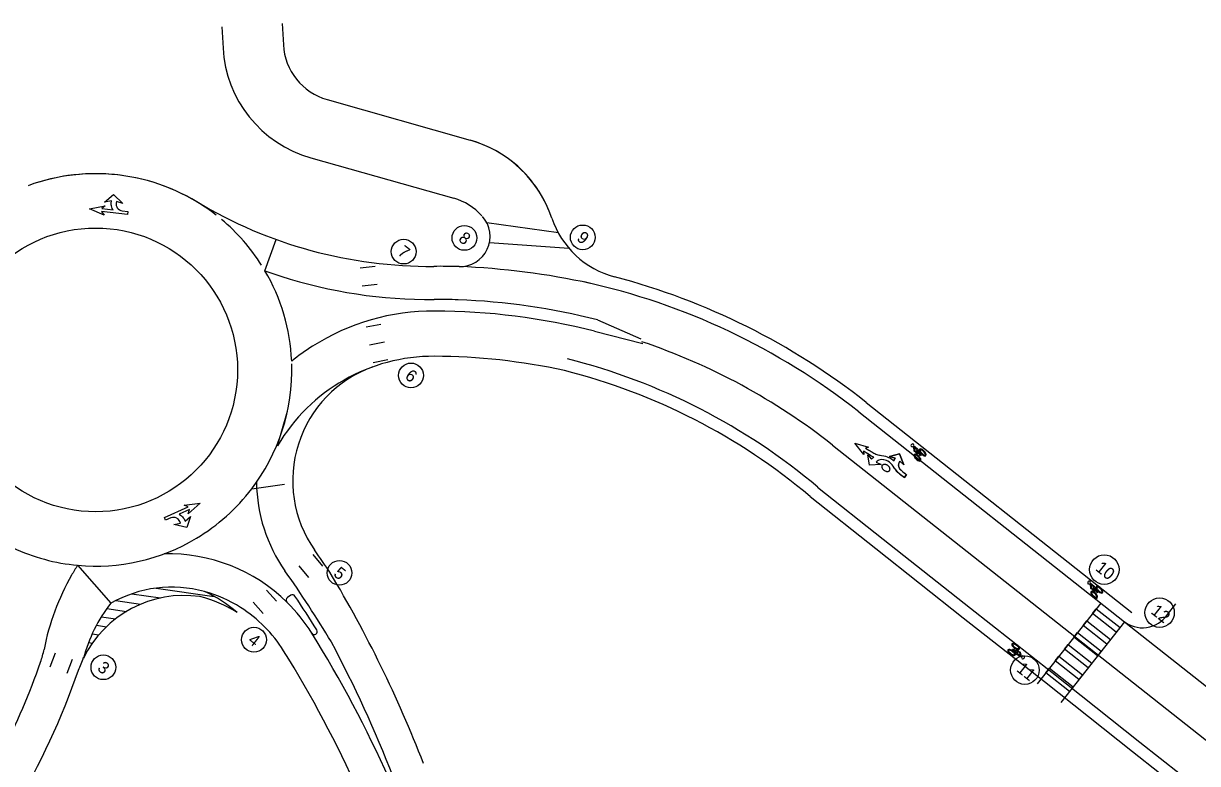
# Model space of a CAD drawing. Extents: x 553958 to 562499, y 493978 to 516388.
# Drawn here: x 561765 to 562153.9, y 497670.2 to 497915.3 of the extents above; entities that cross this region are included whole.
import ezdxf

# ---------------------------------------------------------------- set-up
doc = ezdxf.new("R2010")
doc.units = 0
for name, color, linetype in [('Exist Horizontal Alignment', 7, 'Continuous'), ('Old_Level_1', 7, 'Continuous'), ('Prop Conc Shoulder Berm Gutter', 7, 'Continuous'), ('Prop Dimension', 7, 'Continuous'), ('Prop Drainage Structure Gutter Shoulder Berm Label', 7, 'Continuous'), ('Prop DSN Text', 7, 'Continuous'), ('Prop EOT', 7, 'Continuous'), ('Prop Horizontal Alignment Tick Small', 7, 'Continuous'), ('Prop SS Cut Line', 7, 'Continuous'), ('Prop SS Fill Line', 7, 'Continuous'), ('Prop SS Transition Line', 7, 'Continuous'), ('Scratch_Level_4', 7, 'Continuous'), ('Sheet Plot Border Inside CELL', 7, 'Continuous'), ('Sheet Plot Border Outside CELL', 7, 'Continuous')]:
    doc.layers.add(name, color=color, linetype=linetype)

msp = doc.modelspace()

# ---------------------------------------------------------------- linework, layer by layer
at = {"layer": 'Exist Horizontal Alignment'}
msp.add_circle((561788.88, 497800.56), 47, dxfattribs=at)
at = {"layer": 'Old_Level_1'}
for centre, radius, start, end in [((561902.83, 497610.87), 213, 88.3516, 90.4946), ((561900.37, 497600.07), 220, 75.852, 89.7953), ((561900.37, 497600.07), 220, 75.852, 89.7953), ((561742.33, 497713.69), 30, 340.6791, 349.0323)]:
    msp.add_arc(centre, radius, start, end, dxfattribs=at)
at = {"layer": 'Prop Conc Shoulder Berm Gutter'}
for p, q in [((561840.59, 497761.18), (561851.48, 497762.72)), ((561782.89, 497735.84), (561793.95, 497723.27))]:
    msp.add_line(p, q, dxfattribs=at)
msp.add_lwpolyline([(561844.97, 497833.41), (561848.7, 497843.76), (561848.7, 497843.76)], dxfattribs=at)
at = {"layer": 'Prop Dimension'}
msp.add_arc((561902.83, 497610.87), 228, 51.6978, 75.2698, dxfattribs=at)
at = {"layer": 'Prop Drainage Structure Gutter Shoulder Berm Label'}
for points in [[(561799.47, 497852.06), (561790.85, 497852.99), (561791.73, 497851.81), (561786.84, 497853.93), (561792.07, 497854.95), (561790.96, 497853.99), (561794.71, 497853.58), (561794.39, 497854.07), (561794.22, 497854.45), (561794.11, 497854.91), (561794.07, 497855.28), (561794.06, 497855.75), (561794.17, 497856.57), (561791.86, 497856.15), (561794.74, 497858.69), (561797.93, 497855.66), (561795.74, 497856.4), (561795.69, 497855.75), (561795.66, 497855.37), (561795.72, 497854.98), (561795.86, 497854.62), (561796.01, 497854.27), (561796.32, 497853.9), (561796.73, 497853.6), (561797.17, 497853.39), (561797.69, 497853.25), (561799.57, 497853.05)], [(561799.47, 497852.06), (561790.85, 497852.99), (561791.73, 497851.81), (561786.84, 497853.93), (561792.07, 497854.95), (561790.96, 497853.99), (561794.71, 497853.58), (561794.39, 497854.07), (561794.22, 497854.45), (561794.11, 497854.91), (561794.07, 497855.28), (561794.06, 497855.75), (561794.17, 497856.57), (561791.86, 497856.15), (561794.74, 497858.69), (561797.93, 497855.66), (561795.74, 497856.4), (561795.69, 497855.75), (561795.66, 497855.37), (561795.72, 497854.98), (561795.86, 497854.62), (561796.01, 497854.27), (561796.32, 497853.9), (561796.73, 497853.6), (561797.17, 497853.39), (561797.69, 497853.25), (561799.57, 497853.05)], [(561811.63, 497751.64), (561819.54, 497755.19), (561818.18, 497755.77), (561823.47, 497756.41), (561819.48, 497752.88), (561819.95, 497754.28), (561816.51, 497752.74), (561817.03, 497752.47), (561817.36, 497752.23), (561817.69, 497751.89), (561817.92, 497751.59), (561818.16, 497751.19), (561818.48, 497750.43), (561820.26, 497751.96), (561819.07, 497748.31), (561814.78, 497749.31), (561817.04, 497749.78), (561816.76, 497750.36), (561816.59, 497750.71), (561816.34, 497751.02), (561816.04, 497751.25), (561815.73, 497751.48), (561815.27, 497751.65), (561814.77, 497751.7), (561814.28, 497751.66), (561813.77, 497751.51), (561812.04, 497750.73)], [(561811.63, 497751.64), (561819.54, 497755.19), (561818.18, 497755.77), (561823.47, 497756.41), (561819.48, 497752.88), (561819.95, 497754.28), (561816.51, 497752.74), (561817.03, 497752.47), (561817.36, 497752.23), (561817.69, 497751.89), (561817.92, 497751.59), (561818.16, 497751.19), (561818.48, 497750.43), (561820.26, 497751.96), (561819.07, 497748.31), (561814.78, 497749.31), (561817.04, 497749.78), (561816.76, 497750.36), (561816.59, 497750.71), (561816.34, 497751.02), (561816.04, 497751.25), (561815.73, 497751.48), (561815.27, 497751.65), (561814.77, 497751.7), (561814.28, 497751.66), (561813.77, 497751.51), (561812.04, 497750.73)]]:
    msp.add_lwpolyline(points, close=True, dxfattribs=at)
at = {"layer": 'Prop DSN Text'}
for centre, radius in [((561911.07, 497844.28), 4.11), ((561950.26, 497844.46), 4.1), ((561890.93, 497839.75), 4.1), ((561893.35, 497798.72), 4.1), ((562123.04, 497734.41), 4.89), ((561869.66, 497733.33), 4.09), ((562141.37, 497720.15), 4.87), ((561841.33, 497711.17), 4.12), ((561791.43, 497702.04), 4.09), ((562096.72, 497701.12), 4.73)]:
    msp.add_circle(centre, radius, dxfattribs=at)
at = {"layer": 'Prop EOT'}
msp.add_line((561849.14, 497775.43), (561852.42, 497786.87), dxfattribs=at)
msp.add_lwpolyline([(562043.41, 497772.58), (562040.35, 497776.27), (562044.97, 497774.99), (562043.97, 497774.69), (562045.06, 497773.99), (562045.43, 497773.75), (562045.79, 497773.52), (562046.01, 497773.39), (562046.37, 497773.18), (562046.68, 497772.99), (562046.99, 497772.83), (562047.4, 497772.65), (562047.72, 497772.54), (562047.97, 497772.47), (562048.17, 497772.42), (562048.53, 497772.34), (562048.82, 497772.29), (562049.25, 497772.23), (562049.98, 497772.11), (562050.51, 497771.98), (562051.11, 497771.78), (562051.59, 497771.59), (562052.18, 497771.28), (562052.67, 497770.97), (562053, 497770.72), (562053.37, 497770.39), (562053.47, 497770.67), (562053.62, 497771), (562053.76, 497771.28), (562051.91, 497771.84), (562055.23, 497772.76), (562056.63, 497769.12), (562055.26, 497770.33), (562055.08, 497769.96), (562054.99, 497769.77), (562054.92, 497769.59), (562054.87, 497769.41), (562054.83, 497769.25), (562054.8, 497768.98), (562054.81, 497768.83), (562054.87, 497768.56), (562054.92, 497768.42), (562054.99, 497768.25), (562055.1, 497768.05), (562055.24, 497767.85), (562055.36, 497767.72), (562055.61, 497767.44), (562055.83, 497767.21), (562056.08, 497766.97), (562056.36, 497766.73), (562056.6, 497766.54), (562056.93, 497766.3), (562057.22, 497766.11), (562057.49, 497765.95), (562056.82, 497764.92), (562056.51, 497765.13), (562055.89, 497765.57), (562055.28, 497766.04), (562054.69, 497766.55), (562054.31, 497766.95), (562053.93, 497767.42), (562053.68, 497767.79), (562053.47, 497768.15), (562053.13, 497768.67), (562052.75, 497769.16), (562052.37, 497769.58), (562051.93, 497769.95), (562051.38, 497770.3), (562050.9, 497770.53), (562050.45, 497770.68), (562050.01, 497770.8), (562049.85, 497770.8), (562049.21, 497770.83), (562048.81, 497770.8), (562048.35, 497770.67), (562048.07, 497770.53), (562047.84, 497770.36), (562047.45, 497769.96), (562049.12, 497769.2), (562045.23, 497768.99), (562044.71, 497772.39), (562045.97, 497770.94), (562046.16, 497771.2), (562046.33, 497771.38), (562046.54, 497771.56), (562046.64, 497771.64), (562046.17, 497771.88), (562045.66, 497772.15), (562045.23, 497772.42), (562044.69, 497772.77), (562043.26, 497773.69)], close=True, dxfattribs=at)
for points in [[(562055.26, 497770.33), (562056.63, 497769.12), (562055.23, 497772.76), (562051.91, 497771.84), (562053.76, 497771.28)], [(562056.82, 497764.92), (562057.49, 497765.95)]]:
    msp.add_lwpolyline(points, dxfattribs=at)
for centre, radius, start, end in [((561899.51, 497586.03), 248.94, 77.6632, 87.7507), ((562058.77, 497768.52), 5.72, 151.1501, 160.8548), ((562059.61, 497767.91), 4.97, 150.9846, 159.0255), ((562050.12, 497768.47), 0.777, 171.4542, 191.6551), ((562050.09, 497768.48), 0.742, 148.3406, 171.4542), ((562050.73, 497768.6), 1.4, 191.6551, 214.3846), ((562049.98, 497768.55), 0.613, 147.1072, 148.3406), ((562049.98, 497768.55), 0.613, 145.8738, 147.1072), ((562050.08, 497768.47), 0.742, 122.7602, 145.8738), ((562051.23, 497768.94), 2.01, 214.3846, 222.3695), ((562050.1, 497768.44), 0.777, 102.5592, 122.7602), ((562051.3, 497769.01), 2.1, 222.3695, 235.0686), ((562050.24, 497767.84), 1.4, 79.8298, 102.5592), ((562051.23, 497768.91), 1.98, 235.0686, 237.1072), ((562051.23, 497768.91), 1.98, 237.1072, 239.1457), ((562051.29, 497769.01), 2.1, 239.1457, 251.8449), ((562050.13, 497767.23), 2.01, 71.8449, 79.8298), ((562051.27, 497768.92), 2.01, 251.8449, 259.8298), ((562050.1, 497767.15), 2.1, 59.1457, 71.8449), ((562051.16, 497768.32), 1.4, 259.8298, 282.5592), ((562050.16, 497767.25), 1.98, 57.1072, 59.1457), ((562050.16, 497767.25), 1.98, 55.0686, 57.1072), ((562050.09, 497767.15), 2.1, 42.3695, 55.0686), ((562051.29, 497767.71), 0.777, 282.5592, 302.7602), ((562050.16, 497767.21), 2.01, 34.3846, 42.3695), ((562051.31, 497767.68), 0.742, 302.7602, 325.8738), ((562050.67, 497767.56), 1.4, 11.6551, 34.3846), ((562051.42, 497767.61), 0.613, 327.1072, 328.3406), ((562051.42, 497767.61), 0.613, 325.8738, 327.1072), ((562051.31, 497767.68), 0.742, 328.3406, 351.4542), ((562051.27, 497767.69), 0.777, 351.4542, 11.6551), ((562042.44, 497761.49), 12.88, 28.8167, 31.1161), ((562059.72, 497771.72), 7.21, 213.8512, 231.8501), ((562056.74, 497768.92), 1.93, 156.5912, 179.6833), ((562056.67, 497769.08), 1.88, 184.3573, 200.5072), ((562056.85, 497769.16), 2.07, 201.0235, 219.2305), ((562061.6, 497773.07), 8.23, 219.4223, 240.017), ((562069.38, 497783.85), 22.71, 231.5884, 236.4475)]:
    msp.add_arc(centre, radius, start, end, dxfattribs=at)
at = {"layer": 'Prop Horizontal Alignment Tick Small'}
for p, q in [((562059.15, 497775.07), (562059.26, 497775.18)), ((562059.15, 497775.07), (562059.26, 497775.18)), ((562059.85, 497775.75), (562059.96, 497775.86)), ((562059.85, 497775.75), (562059.96, 497775.86)), ((562059.96, 497774.99), (562060.12, 497775.28)), ((562060.02, 497773.65), (562059.96, 497774.99)), ((562060.12, 497775.28), (562061.36, 497774.15)), ((562060.99, 497774.07), (562060.18, 497774.8)), ((562060.18, 497774.8), (562060.24, 497773.43)), ((562060.59, 497773.14), (562060.99, 497774.07)), ((562061.36, 497774.15), (562062.24, 497772.23)), ((562060.24, 497773.43), (562060.02, 497773.65)), ((562061.29, 497772.67), (562060.59, 497773.14)), ((562060.85, 497771.23), (562060.68, 497771.06)), ((562060.85, 497771.23), (562060.68, 497771.06)), ((562061.19, 497773.94), (562060.89, 497773.22)), ((562060.89, 497773.22), (562061.43, 497772.86)), ((562062.03, 497772.13), (562061.19, 497773.94)), ((562061.43, 497772.86), (562061.29, 497772.67)), ((562061.61, 497771.97), (562061.44, 497771.8)), ((562061.61, 497771.97), (562061.44, 497771.8)), ((562062.24, 497772.23), (562062.04, 497772.11)), ((562062.6, 497772.93), (562062.43, 497772.76)), ((562062.6, 497772.93), (562062.43, 497772.76)), ((562063.36, 497773.67), (562063.19, 497773.5)), ((562063.36, 497773.67), (562063.19, 497773.5)), ((562117.7, 497729.63), (562117.81, 497729.74)), ((562117.7, 497729.63), (562117.81, 497729.74)), ((562118.4, 497730.31), (562118.51, 497730.41)), ((562118.4, 497730.31), (562118.51, 497730.41)), ((562118.51, 497729.55), (562118.67, 497729.83)), ((562118.57, 497728.2), (562118.51, 497729.55)), ((562118.78, 497727.98), (562118.57, 497728.2)), ((562118.67, 497729.83), (562119.9, 497728.71)), ((562119.54, 497728.62), (562118.73, 497729.36)), ((562118.73, 497729.36), (562118.78, 497727.98)), ((562119.14, 497727.69), (562119.54, 497728.62)), ((562119.84, 497727.22), (562119.14, 497727.69)), ((562119.74, 497728.5), (562119.43, 497727.78)), ((562119.43, 497727.78), (562119.97, 497727.42)), ((562120.57, 497726.69), (562119.74, 497728.5)), ((562119.97, 497727.42), (562119.84, 497727.22)), ((562119.9, 497728.71), (562120.79, 497726.79)), ((562121.15, 497727.49), (562120.98, 497727.32)), ((562121.15, 497727.49), (562120.98, 497727.32)), ((562121.91, 497728.23), (562121.74, 497728.06)), ((562121.91, 497728.23), (562121.74, 497728.06)), ((562119.4, 497725.78), (562119.22, 497725.61)), ((562119.4, 497725.78), (562119.22, 497725.61)), ((562120.16, 497726.52), (562119.98, 497726.35)), ((562120.16, 497726.52), (562119.98, 497726.35)), ((562120.79, 497726.79), (562120.58, 497726.66)), ((562092.75, 497708.05), (562092.93, 497708.21)), ((562093.99, 497706.34), (562092.75, 497708.05)), ((562092.94, 497708.19), (562094.11, 497706.58)), ((562093.32, 497708.43), (562093.46, 497708.63)), ((562093.32, 497708.43), (562093.46, 497708.63)), ((562093.92, 497709.3), (562094.06, 497709.5)), ((562093.92, 497709.3), (562094.06, 497709.5)), ((562091.93, 497706.42), (562092.07, 497706.62)), ((562091.93, 497706.42), (562092.07, 497706.62)), ((562092.53, 497707.29), (562092.67, 497707.49)), ((562092.53, 497707.29), (562092.67, 497707.49)), ((562093.67, 497707.59), (562093.77, 497707.81)), ((562094.27, 497707.34), (562093.67, 497707.59)), ((562093.77, 497707.81), (562094.54, 497707.48)), ((562095.42, 497705.47), (562093.99, 497706.34)), ((562094.11, 497706.58), (562094.27, 497707.34)), ((562094.54, 497707.48), (562094.34, 497706.49)), ((562094.34, 497706.49), (562095.27, 497705.92)), ((562094.95, 497707.27), (562095.2, 497707.09)), ((562095.27, 497705.92), (562094.95, 497707.27)), ((562095.2, 497707.09), (562095.52, 497705.78)), ((562095.52, 497705.78), (562095.42, 497705.47)), ((562095.78, 497705.06), (562095.69, 497704.93)), ((562095.78, 497705.06), (562095.69, 497704.93)), ((562096.33, 497705.86), (562096.25, 497705.73)), ((562096.33, 497705.86), (562096.25, 497705.73))]:
    msp.add_line(p, q, dxfattribs=at)
for centre, radius, start, end in [((562059.56, 497775.47), 0.563, 44.1816, 224.1816), ((562059.56, 497775.47), 0.563, 44.1816, 224.1816), ((562059.56, 497775.47), 0.41, 224.1816, 44.1816), ((562118.1, 497730.02), 0.563, 44.1816, 224.1816), ((562118.1, 497730.02), 0.563, 44.1816, 224.1816), ((562118.1, 497730.02), 0.41, 224.1816, 44.1816), ((562096.01, 497705.4), 0.41, 55.3448, 235.3448), ((562096.01, 497705.4), 0.563, 235.3448, 55.3448), ((562096.01, 497705.4), 0.563, 235.3448, 55.3448)]:
    msp.add_arc(centre, radius, start, end, dxfattribs=at)
for centre, major_axis, ratio, start_param, end_param in [((562062.9, 497773.22), (1.04, -1.07), 0.435841, 1.570796, 4.712389), ((562062.9, 497773.22), (0.872, -0.897), 0.325967, 1.570796, 4.712389), ((562061.14, 497771.51), (1.04, -1.07), 0.435841, 1.570796, 4.712389), ((562061.14, 497771.51), (0.872, -0.897), 0.325967, 1.570796, 4.712389), ((562061.14, 497771.51), (1.04, -1.07), 0.435841, 4.712389, 7.853982), ((562061.14, 497771.51), (0.872, -0.897), 0.325967, 4.712389, 7.853982), ((562062.9, 497773.22), (1.04, -1.07), 0.435841, 4.712389, 7.853982), ((562062.9, 497773.22), (0.872, -0.897), 0.325967, 4.712389, 7.853982), ((562119.69, 497726.07), (1.04, -1.07), 0.435841, 1.570796, 4.712389), ((562121.44, 497727.77), (1.04, -1.07), 0.435841, 1.570796, 4.712389), ((562121.44, 497727.77), (0.872, -0.897), 0.325967, 1.570796, 4.712389), ((562121.44, 497727.77), (1.04, -1.07), 0.435841, 4.712389, 7.853982), ((562121.44, 497727.77), (0.872, -0.897), 0.325967, 4.712389, 7.853982), ((562119.69, 497726.07), (0.872, -0.897), 0.325967, 1.570796, 4.712389), ((562119.69, 497726.07), (1.04, -1.07), 0.435841, 4.712389, 7.853982), ((562119.69, 497726.07), (0.872, -0.897), 0.325967, 4.712389, 7.853982), ((562092.3, 497706.96), (-1.23, 0.85), 0.435841, 4.712389, 7.853982), ((562093.69, 497708.97), (-1.23, 0.85), 0.435841, 4.712389, 7.853982), ((562093.69, 497708.97), (-1.03, 0.71), 0.325967, 4.712389, 7.853982), ((562093.69, 497708.97), (-1.23, 0.85), 0.435841, 1.570796, 4.712389), ((562093.69, 497708.97), (-1.03, 0.71), 0.325967, 1.570796, 4.712389), ((562092.3, 497706.96), (-1.03, 0.71), 0.325967, 4.712389, 7.853982), ((562092.3, 497706.96), (-1.23, 0.85), 0.435841, 1.570796, 4.712389), ((562092.3, 497706.96), (-1.03, 0.71), 0.325967, 1.570796, 4.712389)]:
    msp.add_ellipse(centre, major_axis=major_axis, ratio=ratio, start_param=start_param, end_param=end_param, dxfattribs=at)
at = {"layer": 'Prop SS Cut Line'}
for start, end in [(32.2245, 50.0996), (322.2626, 1.7403), (264.7081, 300.8864)]:
    msp.add_arc((561788.88, 497800.56), 65, start, end, dxfattribs=at)
at = {"layer": 'Prop SS Fill Line'}
for p, q in [((561808.89, 497728.27), (561828.17, 497725.5)), ((561795.53, 497724.13), (561803.76, 497722.94)), ((561800.86, 497726.39), (561810.39, 497725.02)), ((561853.52, 497725.92), (561852.4, 497725.16)), ((561853.52, 497725.92), (561852.4, 497725.16)), ((561792.62, 497721.52), (561799.1, 497720.58)), ((561833.03, 497721.77), (561834.03, 497721.62)), ((561789.13, 497715.96), (561792.43, 497715.48)), ((561790.76, 497718.75), (561795.44, 497718.08)), ((561787.72, 497713.13), (561789.92, 497712.81)), ((561786.52, 497710.27), (561787.82, 497710.08)), ((561785.5, 497707.39), (561786.05, 497707.31))]:
    msp.add_line(p, q, dxfattribs=at)
for centre, radius, start, end in [((561894.15, 497763.9), 40, 109.6905, 215.064), ((561520.91, 497501.94), 416, 33.7822, 35.064), ((561509.72, 497519.68), 415.96, 21.2102, 30.9138), ((561814.08, 497687.9), 40.7, 74.6012, 119.6398), ((561818.11, 497688.84), 37, 81.7233, 154.1829), ((561812.93, 497683.75), 43, 57.9357, 75.8659), ((561812.93, 497683.75), 45, 57.8217, 74.6017), ((561806.78, 497686.79), 44.23, 49.0588, 65.8388), ((561852.96, 497724.34), 1, 123.9566, 225.3932), ((561852.96, 497724.34), 1, 123.9566, 225.3932), ((561812.93, 497683.75), 56, 31.9071, 45.3932), ((561812.93, 497683.75), 56, 31.9071, 45.3932), ((561854.08, 497725.09), 1, 33.8137, 123.9566), ((561854.08, 497725.09), 1, 33.8137, 123.9566), ((561520.91, 497501.94), 402, 31.9071, 33.8137), ((561520.91, 497501.94), 402, 31.9071, 33.8137), ((561833.06, 497692.3), 49.89, 141.6233, 165.3125), ((561812.93, 497683.75), 45, 31.9071, 57.8217), ((561861.32, 497713.88), 1, 211.9071, 31.9071), ((561861.32, 497713.88), 1, 211.9071, 31.9071), ((561520.91, 497501.94), 389, 24.0786, 31.9071)]:
    msp.add_arc(centre, radius, start, end, dxfattribs=at)
at = {"layer": 'Prop SS Transition Line'}
for centre, radius, start, end in [((561899.61, 497984.86), 161, 250.1623, 252.1253), ((561788.88, 497800.56), 65, 2.5556, 30.3573), ((561900.89, 497745.07), 75, 122.3906, 128.8766), ((561788.88, 497800.56), 65, 300.8864, 322.7028), ((561788.88, 497800.56), 65, 245.0024, 264.7081), ((561850.55, 497692.72), 80.24, 147.4917, 150.2316)]:
    msp.add_arc(centre, radius, start, end, dxfattribs=at)
at = {"layer": 'Scratch_Level_4'}
for p, q in [((561918.42, 497849.41), (561942.21, 497846.03)), ((561919.36, 497842.76), (561945.68, 497840.84)), ((561876.48, 497834.35), (561881.45, 497834.94)), ((561877.19, 497828.4), (561882.15, 497828.98)), ((561878.46, 497814.78), (561883.36, 497815.75)), ((561879.63, 497808.89), (561884.53, 497809.87)), ((561880.8, 497803.01), (561885.71, 497803.98)), ((561860.85, 497739.43), (561864.02, 497735.56)), ((561856.21, 497735.63), (561859.37, 497731.76)), ((561845.48, 497727.63), (561848.84, 497723.93)), ((561841.04, 497723.59), (561844.4, 497719.9)), ((562121.89, 497723.3), (562100.82, 497696.62)), ((562129.74, 497717.1), (562108.67, 497690.42)), ((561775.44, 497706.76), (561773.67, 497702.09)), ((561781.05, 497704.64), (561779.28, 497699.96))]:
    msp.add_line(p, q, dxfattribs=at)
for points in [[(562120.4, 497721.42), (562128.25, 497715.22), (562127.01, 497713.65), (562119.17, 497719.85)], [(562117.31, 497717.49), (562125.15, 497711.29), (562123.91, 497709.72), (562116.07, 497715.92)], [(562114.21, 497713.57), (562122.05, 497707.37), (562120.81, 497705.8), (562112.97, 497712)], [(562111.11, 497709.64), (562118.96, 497703.45), (562117.72, 497701.88), (562109.87, 497708.07)], [(562108.01, 497705.72), (562115.86, 497699.52), (562114.62, 497697.95), (562106.77, 497704.15)], [(562104.91, 497701.8), (562112.76, 497695.6), (562111.52, 497694.03), (562103.67, 497700.23)]]:
    msp.add_lwpolyline(points, close=True, dxfattribs=at)
at = {"layer": 'Sheet Plot Border Inside CELL'}
for p, q in [((561830.7, 497914.23), (561831.09, 497907.16)), ((561830.7, 497914.23), (561831.09, 497907.16)), ((561850.68, 497915.31), (561851.06, 497908.25)), ((561865.57, 497890.09), (561912.97, 497876.65)), ((561860.12, 497870.85), (561907.51, 497857.41)), ((562044.15, 497789.8), (562132.21, 497720.25)), ((562041.67, 497786.66), (562129.73, 497717.11)), ((562143.95, 497719.52), (562146.74, 497723.06)), ((562129.73, 497717.11), (562170.43, 497684.96))]:
    msp.add_line(p, q, dxfattribs=at)
for points in [[(562025.59, 497758.62), (562047.32, 497741.36), (562076.25, 497718.46), (562103.19, 497697.29), (562132.35, 497674.11), (562159.25, 497652.91), (562187.11, 497630.9), (562212.55, 497611), (562239.91, 497589.56), (562267.38, 497568.14), (562294.58, 497546.77), (562304.18, 497539.17), (562305.88, 497537.9), (562320.69, 497526.24), (562322.63, 497524.82), (562324.12, 497523.75), (562333.77, 497516.21)], [(562028.08, 497761.75), (562049.81, 497744.49), (562078.73, 497721.6), (562105.67, 497700.43), (562134.83, 497677.25), (562161.73, 497656.05), (562189.58, 497634.04), (562215.01, 497614.15), (562242.38, 497592.72), (562269.85, 497571.29), (562297.06, 497549.91), (562306.61, 497542.35), (562308.31, 497541.08), (562323.11, 497529.42), (562324.98, 497528.05), (562326.52, 497526.94), (562336.28, 497519.33), (562336.33, 497519.29)]]:
    msp.add_lwpolyline(points, dxfattribs=at)
for centre, radius, start, end in [((561871.03, 497909.33), 40, 183.1076, 254.1712), ((561871.03, 497909.33), 20, 183.1076, 254.1712), ((561902.06, 497838.17), 40, 22.3396, 74.1712), ((561902.06, 497838.17), 40, 18.5083, 74.1712), ((561788.88, 497800.56), 65, 53.3556, 110.1477), ((561788.88, 497800.56), 65, 52.0514, 106.7883), ((561899.61, 497984.86), 150, 239.0027, 270.4946), ((561902.06, 497838.17), 20, 42.3283, 74.1712), ((561909.57, 497844.78), 10, 268.3516, 41.3275), ((561968.44, 497860.39), 30, 198.5083, 255.2698), ((561902.83, 497610.87), 224, 88.3516, 90.4946), ((561899.61, 497984.86), 161, 252.1253, 270.4946), ((561902.83, 497610.87), 224, 51.6978, 77.6454), ((561902.83, 497610.87), 228, 51.6978, 75.2698), ((561902.83, 497610.87), 213, 88.3516, 90.4946), ((561900.37, 497600.07), 223.88, 75.8435, 87.8013), ((561900.89, 497745.07), 75, 89.7953, 122.3906), ((561900.37, 497600.07), 220, 75.852, 89.7953), ((561900.89, 497745.07), 60, 89.7953, 149.6054), ((561900.37, 497600.07), 205, 77.6543, 89.7953), ((561894.4, 497602.9), 207.62, 49.8846, 75.841), ((561894.4, 497602.9), 203.62, 49.8846, 75.841), ((561894.15, 497763.9), 52, 180.6427, 215.064), ((561812.85, 497683.17), 56.47, 45.7438, 91.3398), ((561850.55, 497692.72), 80.24, 150.2316, 169.0323), ((561520.91, 497501.94), 404, 31.0682, 35.064), ((562135.68, 497725.14), 10, 229.924, 325.7883), ((561742.33, 497713.69), 30, 340.6791, 349.0323), ((561509.72, 497519.68), 404.97, 21.1448, 28.0992), ((561754.1, 497714.97), 32.23, 334.4529, 342.8061), ((561534.03, 497788.33), 264, 318.8639, 340.6981), ((561531.14, 497787.73), 253.79, 333.2802, 340.6791)]:
    msp.add_arc(centre, radius, start, end, dxfattribs=at)
at = {"layer": 'Sheet Plot Border Outside CELL'}
msp.add_line((562032.99, 497775.67), (562315.4, 497552.62), dxfattribs=at)
for points in [[(561955.13, 497817.15), (561969.48, 497810.85), (561969.48, 497810.85), (561969.48, 497810.85), (561969.48, 497810.85)], [(561954.15, 497813.4), (561970.16, 497809.32), (561970.16, 497809.32)]]:
    msp.add_lwpolyline(points, dxfattribs=at)
for centre, radius, start, end in [((561902.83, 497610.87), 210, 51.6978, 71.3841), ((561520.91, 497501.94), 400, 24.0786, 31.9071)]:
    msp.add_arc(centre, radius, start, end, dxfattribs=at)

# ---------------------------------------------------------------- texts
at = {"layer": 'Prop EOT'}
for s, p in [('8', (561908.78, 497843.54)), ('9', (561947.98, 497843.71)), ('7', (561888.65, 497839.01)), ('6', (561891.06, 497797.98)), ('5', (561867.39, 497732.57)), ('10', (562119.86, 497734.38)), ('12', (562138.2, 497720.11)), ('4', (561839.03, 497710.44)), ('3', (561789.16, 497701.29)), ('11', (562093.69, 497700.96))]:
    msp.add_text(s, height=4, rotation=321.6667, dxfattribs=at).set_placement(p)

doc.saveas('drawing.dxf')
